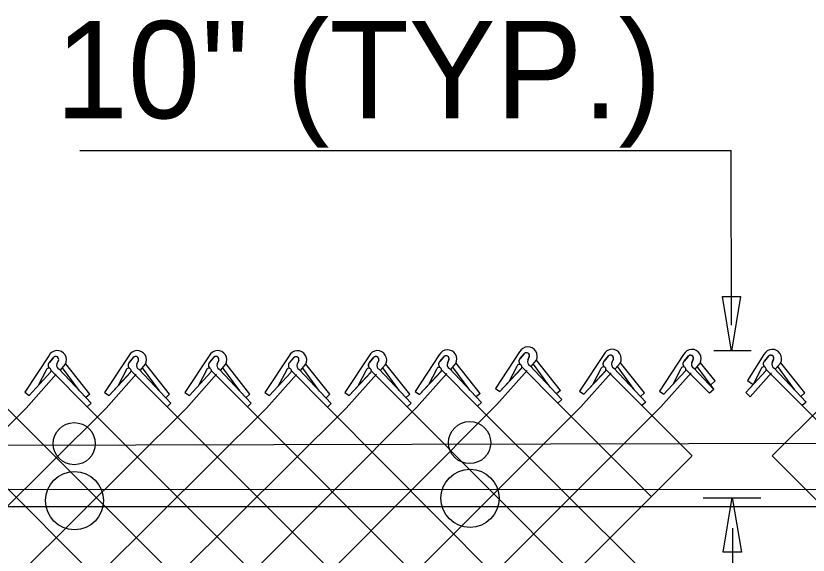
# Model space of a CAD drawing. Extents: x 0 to 2.85, y -0.1 to 1.83.
# Drawn here: x 1.3272 to 1.407, y 1.3817 to 1.436 of the extents above; entities that cross this region are included whole.
import ezdxf

# ---------------------------------------------------------------- set-up
doc = ezdxf.new("R2010")
doc.units = 0
for name, color, linetype in [('CT_Dimensions', 7, 'Continuous'), ('sb_Chainlink Fence', 7, 'Continuous'), ('sb_Existing Structural Steel', 7, 'Continuous')]:
    doc.layers.add(name, color=color, linetype=linetype)

msp = doc.modelspace()

# ---------------------------------------------------------------- linework, layer by layer
at = {"layer": 'CT_Dimensions'}
for p, q in [((1.333672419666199, 1.4224212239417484), (1.3992727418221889, 1.4224212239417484)), ((1.3993275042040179, 1.404847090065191), (1.3992727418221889, 1.4224212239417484)), ((1.397543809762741, 1.4022854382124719), (1.4012953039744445, 1.4022854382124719)), ((1.3964543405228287, 1.3874493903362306), (1.4022773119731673, 1.3874493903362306)), ((1.399430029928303, 1.376108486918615), (1.399430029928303, 1.3843877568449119))]:
    msp.add_line(p, q, dxfattribs=at)
for points in [[(1.4002339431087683, 1.407721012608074), (1.3993178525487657, 1.4022244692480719), (1.3984017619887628, 1.407721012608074)], [(1.398477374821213, 1.3819714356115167), (1.3993934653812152, 1.3874679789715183), (1.4003095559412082, 1.3819714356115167)]]:
    msp.add_lwpolyline(points, close=True, dxfattribs=at)
at = {"layer": 'sb_Chainlink Fence'}
for p, q in [((1.330548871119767, 1.401759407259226), (1.3281123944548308, 1.3980704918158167)), ((1.330596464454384, 1.4010906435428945), (1.3310415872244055, 1.4016177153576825)), ((1.331000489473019, 1.401574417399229), (1.330596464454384, 1.4010906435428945)), ((1.338601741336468, 1.401753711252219), (1.33616526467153, 1.3980647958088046)), ((1.3386493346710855, 1.4010849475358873), (1.339094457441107, 1.4016120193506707)), ((1.3390533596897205, 1.401568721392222), (1.3386493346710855, 1.4010849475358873)), ((1.3466944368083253, 1.401756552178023), (1.3442579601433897, 1.3980676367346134)), ((1.3467420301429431, 1.4010877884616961), (1.3471871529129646, 1.4016148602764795)), ((1.3471460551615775, 1.401571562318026), (1.3467420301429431, 1.4010877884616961)), ((1.3547479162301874, 1.4017361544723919), (1.3523114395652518, 1.3980472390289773)), ((1.3547955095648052, 1.40106739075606), (1.3552406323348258, 1.4015944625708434)), ((1.3551995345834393, 1.4015511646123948), (1.3547955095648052, 1.40106739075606)), ((1.3628021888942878, 1.401752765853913), (1.36036571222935, 1.3980638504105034)), ((1.3628497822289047, 1.401084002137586), (1.3632949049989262, 1.4016110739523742)), ((1.3632538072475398, 1.401567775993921), (1.3628497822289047, 1.401084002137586)), ((1.3698771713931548, 1.4018324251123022), (1.3674406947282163, 1.3981435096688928)), ((1.369924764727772, 1.4011636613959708), (1.3703698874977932, 1.4016907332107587)), ((1.370328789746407, 1.40164743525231), (1.369924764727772, 1.4011636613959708)), ((1.3779722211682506, 1.4021346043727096), (1.375535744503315, 1.3984456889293)), ((1.3780198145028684, 1.401465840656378), (1.378464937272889, 1.401992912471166)), ((1.3784238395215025, 1.4019496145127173), (1.3780198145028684, 1.401465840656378)), ((1.3789459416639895, 1.401664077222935), (1.3787823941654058, 1.4013097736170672)), ((1.3787830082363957, 1.401322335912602), (1.3789456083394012, 1.4016560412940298)), ((1.3864391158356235, 1.401884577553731), (1.3840026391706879, 1.3981956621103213)), ((1.3864867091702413, 1.4012158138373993), (1.3869318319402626, 1.4017428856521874)), ((1.3868907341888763, 1.4016995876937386), (1.3864867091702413, 1.4012158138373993)), ((1.394491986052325, 1.4018788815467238), (1.3920555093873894, 1.3981899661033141)), ((1.3945395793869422, 1.4012101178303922), (1.3949847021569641, 1.4017371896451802)), ((1.3949436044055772, 1.4016938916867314), (1.3945395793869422, 1.4012101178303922)), ((1.4025846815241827, 1.4018817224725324), (1.4009332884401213, 1.399278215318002)), ((1.4026322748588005, 1.401212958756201), (1.4030773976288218, 1.4017400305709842)), ((1.4030362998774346, 1.4016967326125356), (1.4026322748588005, 1.401212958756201)), ((1.331522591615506, 1.4012888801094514), (1.3313590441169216, 1.4009345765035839)), ((1.3313596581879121, 1.4009471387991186), (1.3315222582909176, 1.4012808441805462)), ((1.3317059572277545, 1.4002996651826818), (1.3322011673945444, 1.4008858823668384)), ((1.3317125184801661, 1.4003085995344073), (1.3322036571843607, 1.4008879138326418)), ((1.3322011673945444, 1.4008858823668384), (1.3322375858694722, 1.4009539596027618)), ((1.3322375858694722, 1.4009539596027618), (1.3322686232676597, 1.4010268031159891)), ((1.3346619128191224, 1.397894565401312), (1.3322490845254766, 1.4009292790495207)), ((1.3395754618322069, 1.4012831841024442), (1.339411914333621, 1.4009288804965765)), ((1.339412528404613, 1.4009414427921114), (1.3395751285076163, 1.401275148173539)), ((1.339758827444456, 1.4002939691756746), (1.340254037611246, 1.4008801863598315)), ((1.3397653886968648, 1.4003029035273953), (1.3402565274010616, 1.4008822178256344)), ((1.340254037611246, 1.4008801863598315), (1.340290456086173, 1.4009482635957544)), ((1.340290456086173, 1.4009482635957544), (1.3403214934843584, 1.4010211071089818)), ((1.3427147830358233, 1.397888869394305), (1.3403019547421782, 1.4009235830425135)), ((1.3476681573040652, 1.4012860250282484), (1.3475046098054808, 1.4009317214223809)), ((1.3475052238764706, 1.4009442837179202), (1.3476678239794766, 1.401277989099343)), ((1.3478515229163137, 1.4002968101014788), (1.3483467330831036, 1.4008830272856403)), ((1.347858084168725, 1.4003057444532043), (1.34834922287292, 1.4008850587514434)), ((1.3483467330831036, 1.4008830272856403), (1.3483831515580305, 1.4009511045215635)), ((1.3483831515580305, 1.4009511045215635), (1.348414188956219, 1.4010239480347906)), ((1.350807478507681, 1.3978917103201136), (1.3483946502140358, 1.4009264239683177)), ((1.3557216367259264, 1.4012656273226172), (1.3555580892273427, 1.4009113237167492)), ((1.3555587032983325, 1.4009238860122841), (1.355721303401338, 1.4012575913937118)), ((1.3559050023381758, 1.4002764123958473), (1.3564002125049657, 1.4008626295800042)), ((1.3559115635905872, 1.4002853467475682), (1.356402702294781, 1.4008646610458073)), ((1.3564002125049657, 1.4008626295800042), (1.3564366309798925, 1.4009307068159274)), ((1.3564366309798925, 1.4009307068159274), (1.35646766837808, 1.4010035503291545)), ((1.3588609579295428, 1.3978713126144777), (1.356448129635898, 1.4009060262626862)), ((1.3637759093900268, 1.401282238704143), (1.363612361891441, 1.4009279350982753)), ((1.363612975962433, 1.4009404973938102), (1.3637755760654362, 1.4012742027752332)), ((1.3639592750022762, 1.4002930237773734), (1.364454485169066, 1.40087924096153)), ((1.3639658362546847, 1.4003019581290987), (1.3644569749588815, 1.4008812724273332)), ((1.364454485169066, 1.40087924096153), (1.364490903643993, 1.4009473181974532)), ((1.364490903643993, 1.4009473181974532), (1.3645219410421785, 1.4010201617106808)), ((1.3669152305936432, 1.3978879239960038), (1.3645024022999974, 1.4009226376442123)), ((1.3708508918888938, 1.4013618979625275), (1.3706873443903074, 1.40100759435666)), ((1.3706879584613, 1.401020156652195), (1.3708505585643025, 1.4013538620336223)), ((1.3710342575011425, 1.4003726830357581), (1.371529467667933, 1.4009589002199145)), ((1.3710408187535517, 1.4003816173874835), (1.3715319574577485, 1.4009609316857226)), ((1.371529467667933, 1.4009589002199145), (1.37156588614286, 1.4010269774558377)), ((1.37156588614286, 1.4010269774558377), (1.3715969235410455, 1.4010998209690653)), ((1.3739902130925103, 1.3979675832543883), (1.3715773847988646, 1.4010022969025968)), ((1.3789941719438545, 1.4007703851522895), (1.3822196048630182, 1.397343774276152)), ((1.379129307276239, 1.4006748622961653), (1.379624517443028, 1.401261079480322)), ((1.3791358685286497, 1.4006837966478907), (1.3796270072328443, 1.4012631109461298)), ((1.3810462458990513, 1.398601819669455), (1.3793491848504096, 1.400911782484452)), ((1.379624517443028, 1.401261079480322), (1.3796609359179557, 1.4013291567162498)), ((1.3796609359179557, 1.4013291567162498), (1.3796919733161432, 1.4014020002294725)), ((1.382085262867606, 1.3982697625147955), (1.379672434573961, 1.4013044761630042)), ((1.3874128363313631, 1.401414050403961), (1.3872492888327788, 1.4010597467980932)), ((1.3872499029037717, 1.4010723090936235), (1.3874125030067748, 1.4014060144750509)), ((1.3875962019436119, 1.4004248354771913), (1.388091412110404, 1.401011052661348)), ((1.3876027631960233, 1.400433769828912), (1.3880939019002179, 1.401013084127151)), ((1.388091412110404, 1.401011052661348), (1.3881278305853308, 1.4010791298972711)), ((1.3881278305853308, 1.4010791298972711), (1.388158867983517, 1.4011519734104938)), ((1.3905521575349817, 1.3980197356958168), (1.3881393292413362, 1.4010544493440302)), ((1.395465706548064, 1.4014083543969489), (1.3953021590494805, 1.4010540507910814)), ((1.3953027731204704, 1.4010666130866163), (1.3954653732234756, 1.401400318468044)), ((1.3956490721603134, 1.4004191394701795), (1.3961442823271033, 1.4010053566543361)), ((1.3956556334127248, 1.4004280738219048), (1.3961467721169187, 1.401007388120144)), ((1.3961442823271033, 1.4010053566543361), (1.3961807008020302, 1.4010734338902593)), ((1.3961807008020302, 1.4010734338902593), (1.396211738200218, 1.4011462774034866)), ((1.3976529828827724, 1.3992114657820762), (1.3961921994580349, 1.4010487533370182)), ((1.4035584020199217, 1.4014111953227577), (1.403394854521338, 1.4010568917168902)), ((1.4033954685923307, 1.401069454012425), (1.4035580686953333, 1.4014031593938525)), ((1.403741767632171, 1.4004219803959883), (1.4042369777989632, 1.4010081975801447)), ((1.4037483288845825, 1.4004309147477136), (1.404239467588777, 1.401010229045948)), ((1.4042369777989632, 1.4010081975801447), (1.40427339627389, 1.4010762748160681)), ((1.40427339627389, 1.4010762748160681), (1.4043044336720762, 1.4011491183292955)), ((1.406697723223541, 1.3980168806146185), (1.4042848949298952, 1.401051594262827)), ((1.3282564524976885, 1.3964829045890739), (1.3312917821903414, 1.3999005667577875)), ((1.3285583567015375, 1.3977658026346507), (1.330728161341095, 1.4001031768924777)), ((1.3285583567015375, 1.3977658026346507), (1.3307143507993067, 1.4000894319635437)), ((1.3302714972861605, 1.400303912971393), (1.3294598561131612, 1.3987523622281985)), ((1.3307731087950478, 1.4002526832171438), (1.3344004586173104, 1.396609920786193)), ((1.331570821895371, 1.4003951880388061), (1.334796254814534, 1.3969685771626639)), ((1.3336228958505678, 1.3982266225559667), (1.331925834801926, 1.4005365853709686)), ((1.3366112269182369, 1.3977601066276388), (1.338781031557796, 1.4000974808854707)), ((1.3366112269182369, 1.3977601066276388), (1.3387672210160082, 1.4000837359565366)), ((1.3383243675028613, 1.4002982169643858), (1.3375127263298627, 1.3987466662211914)), ((1.3388259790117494, 1.4002469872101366), (1.342453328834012, 1.396604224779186)), ((1.3396236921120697, 1.400389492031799), (1.3428491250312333, 1.396962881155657)), ((1.3416757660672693, 1.3982209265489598), (1.3399787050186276, 1.4005308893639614)), ((1.3447039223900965, 1.3977629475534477), (1.3468737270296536, 1.4001003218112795)), ((1.3447039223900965, 1.3977629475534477), (1.3468599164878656, 1.4000865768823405)), ((1.3464170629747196, 1.4003010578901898), (1.3456054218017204, 1.3987495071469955)), ((1.346918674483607, 1.4002498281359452), (1.3505460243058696, 1.396607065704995)), ((1.3477163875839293, 1.4003923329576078), (1.350941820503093, 1.3969657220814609)), ((1.349768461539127, 1.3982237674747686), (1.3480714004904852, 1.4005337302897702)), ((1.3527574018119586, 1.3977425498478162), (1.3549272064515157, 1.4000799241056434)), ((1.3527574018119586, 1.3977425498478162), (1.3549133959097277, 1.4000661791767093)), ((1.3544705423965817, 1.4002806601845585), (1.3536589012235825, 1.398729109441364)), ((1.354972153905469, 1.4002294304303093), (1.3585995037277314, 1.3965866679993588)), ((1.3557698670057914, 1.4003719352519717), (1.358995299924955, 1.3969453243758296)), ((1.3578219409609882, 1.3982033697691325), (1.3561248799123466, 1.4005133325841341)), ((1.360811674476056, 1.3977591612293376), (1.362981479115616, 1.4000965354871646)), ((1.360811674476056, 1.3977591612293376), (1.3629676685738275, 1.4000827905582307)), ((1.3625248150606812, 1.4002972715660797), (1.361713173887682, 1.3987457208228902)), ((1.3630264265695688, 1.4002460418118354), (1.3666537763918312, 1.3966032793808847)), ((1.3638241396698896, 1.4003885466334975), (1.3670495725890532, 1.3969619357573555)), ((1.3658762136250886, 1.3982199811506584), (1.364179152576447, 1.4005299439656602)), ((1.3675847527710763, 1.39655592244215), (1.3706200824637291, 1.3999735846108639)), ((1.367886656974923, 1.397838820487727), (1.370056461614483, 1.4001761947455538)), ((1.367886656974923, 1.397838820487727), (1.3700426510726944, 1.4001624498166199)), ((1.3695997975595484, 1.400376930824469), (1.3687881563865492, 1.3988253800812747)), ((1.3701014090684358, 1.40032570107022), (1.3737287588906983, 1.3966829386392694)), ((1.3708991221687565, 1.4004682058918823), (1.3741245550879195, 1.3970415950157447)), ((1.3729511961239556, 1.3982996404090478), (1.371254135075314, 1.4006096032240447)), ((1.3756798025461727, 1.3968581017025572), (1.378715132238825, 1.4002757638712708)), ((1.3759817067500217, 1.398140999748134), (1.3781515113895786, 1.4004783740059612)), ((1.3759817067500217, 1.398140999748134), (1.3781377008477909, 1.4004646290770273)), ((1.377694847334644, 1.4006791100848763), (1.3768832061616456, 1.399127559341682)), ((1.3781964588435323, 1.4006278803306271), (1.3818238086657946, 1.3969851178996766)), ((1.3841466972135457, 1.3966080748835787), (1.3871820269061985, 1.4000257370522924)), ((1.3844486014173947, 1.3978909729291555), (1.3866184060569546, 1.4002283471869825)), ((1.3844486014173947, 1.3978909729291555), (1.3866045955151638, 1.4002146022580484)), ((1.38616174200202, 1.4004290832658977), (1.3853501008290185, 1.398877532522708)), ((1.3866633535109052, 1.4003778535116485), (1.3902907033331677, 1.396735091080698)), ((1.3874610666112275, 1.4005203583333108), (1.3906864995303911, 1.3970937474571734)), ((1.389513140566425, 1.3983517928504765), (1.3878160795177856, 1.4006617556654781)), ((1.3921995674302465, 1.3966023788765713), (1.3952348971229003, 1.4000200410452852)), ((1.3925014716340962, 1.3978852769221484), (1.3946712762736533, 1.4002226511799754)), ((1.3925014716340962, 1.3978852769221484), (1.3946574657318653, 1.4002089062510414)), ((1.3942146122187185, 1.4004233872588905), (1.39340297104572, 1.3988718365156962)), ((1.394716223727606, 1.4003721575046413), (1.3970972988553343, 1.3979809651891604)), ((1.395513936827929, 1.4005146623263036), (1.397531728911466, 1.398371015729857)), ((1.3975443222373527, 1.3983756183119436), (1.3958689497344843, 1.400656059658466)), ((1.4007617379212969, 1.3980509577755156), (1.4027639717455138, 1.400225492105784)), ((1.4011838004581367, 1.3985235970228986), (1.402750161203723, 1.40021174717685)), ((1.4011904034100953, 1.3976164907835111), (1.4033275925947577, 1.400022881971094)), ((1.402307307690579, 1.4004262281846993), (1.4014956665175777, 1.398874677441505)), ((1.4028089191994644, 1.40037499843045), (1.4064362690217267, 1.3967322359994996)), ((1.4036066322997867, 1.4005175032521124), (1.4068320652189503, 1.3970908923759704)), ((1.4056587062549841, 1.3983489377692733), (1.4039616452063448, 1.400658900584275)), ((1.33630932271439, 1.3964772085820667), (1.339344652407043, 1.3998948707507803)), ((1.3444020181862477, 1.3964800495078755), (1.3474373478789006, 1.3998977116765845)), ((1.3524554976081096, 1.3964596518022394), (1.3554908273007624, 1.399877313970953)), ((1.3605097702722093, 1.3964762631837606), (1.3635450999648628, 1.3998939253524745)), ((1.3976529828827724, 1.3992114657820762), (1.397222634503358, 1.3988214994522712)), ((1.4009332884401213, 1.399278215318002), (1.4014956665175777, 1.398874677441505)), ((1.375535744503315, 1.3984456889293), (1.3759817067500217, 1.398140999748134)), ((1.397531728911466, 1.398371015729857), (1.3970987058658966, 1.397978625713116)), ((1.3281123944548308, 1.3980704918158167), (1.3285583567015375, 1.3977658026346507)), ((1.3346619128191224, 1.397894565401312), (1.3342661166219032, 1.3975359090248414)), ((1.33616526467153, 1.3980647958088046), (1.3366112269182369, 1.3977601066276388)), ((1.3427147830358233, 1.397888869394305), (1.3423189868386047, 1.3975302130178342)), ((1.3442579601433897, 1.3980676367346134), (1.3447039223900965, 1.3977629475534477)), ((1.350807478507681, 1.3978917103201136), (1.3504116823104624, 1.3975330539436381)), ((1.3523114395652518, 1.3980472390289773), (1.3527574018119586, 1.3977425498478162)), ((1.3588609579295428, 1.3978713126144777), (1.3584651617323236, 1.397512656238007)), ((1.36036571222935, 1.3980638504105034), (1.360811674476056, 1.3977591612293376)), ((1.3669152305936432, 1.3978879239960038), (1.366519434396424, 1.397529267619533)), ((1.3674406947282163, 1.3981435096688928), (1.367886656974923, 1.397838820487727)), ((1.3739902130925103, 1.3979675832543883), (1.3735944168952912, 1.3976089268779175)), ((1.382085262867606, 1.3982697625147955), (1.3816894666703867, 1.397911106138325)), ((1.3840026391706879, 1.3981956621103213), (1.3844486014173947, 1.3978909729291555)), ((1.3905521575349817, 1.3980197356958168), (1.3901563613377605, 1.397661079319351)), ((1.3920555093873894, 1.3981899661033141), (1.3925014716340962, 1.3978852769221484)), ((1.4007617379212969, 1.3980509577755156), (1.4011904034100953, 1.3976164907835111)), ((1.406697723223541, 1.3980168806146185), (1.4063019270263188, 1.3976582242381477)), ((1.2691732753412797, 1.2899304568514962), (1.3756798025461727, 1.3968581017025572)), ((1.317879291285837, 1.3968433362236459), (1.4247986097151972, 1.290038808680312)), ((1.3259335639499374, 1.396859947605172), (1.4329119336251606, 1.2899438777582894)), ((1.334796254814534, 1.3969685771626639), (1.3344004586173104, 1.396609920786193)), ((1.3428491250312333, 1.396962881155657), (1.342453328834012, 1.396604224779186)), ((1.350941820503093, 1.3969657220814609), (1.3505460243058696, 1.396607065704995)), ((1.358995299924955, 1.3969453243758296), (1.3585995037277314, 1.3965866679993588)), ((1.3670495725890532, 1.3969619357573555), (1.3666537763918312, 1.3966032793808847)), ((1.3741245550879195, 1.3970415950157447), (1.3737287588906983, 1.3966829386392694)), ((1.3822196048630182, 1.397343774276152), (1.3818238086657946, 1.3969851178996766)), ((1.3818238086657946, 1.3969851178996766), (1.3912193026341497, 1.3875857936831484)), ((1.3906864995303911, 1.3970937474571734), (1.3902907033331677, 1.396735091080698)), ((1.3902907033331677, 1.396735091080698), (1.3953598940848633, 1.391655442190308)), ((1.4068320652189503, 1.3970908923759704), (1.4064362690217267, 1.3967322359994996)), ((1.4064362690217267, 1.3967322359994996), (1.4554980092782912, 1.3475362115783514)), ((1.2203680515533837, 1.2892561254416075), (1.3282564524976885, 1.3964829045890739)), ((1.2286213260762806, 1.289436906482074), (1.33630932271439, 1.3964772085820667)), ((1.236559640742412, 1.2892719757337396), (1.3444020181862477, 1.3964800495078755)), ((1.2448086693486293, 1.2895248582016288), (1.3524554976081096, 1.3964596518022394)), ((1.2529972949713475, 1.2897002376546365), (1.3605097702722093, 1.3964762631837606)), ((1.2610501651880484, 1.2897059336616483), (1.3675847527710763, 1.39655592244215)), ((1.2771338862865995, 1.2897935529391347), (1.3841466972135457, 1.3966080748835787)), ((1.2855302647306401, 1.2900829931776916), (1.3921995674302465, 1.3966023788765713)), ((1.3344004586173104, 1.396609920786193), (1.440911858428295, 1.2901536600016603)), ((1.342453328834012, 1.396604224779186), (1.4490435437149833, 1.2901329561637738)), ((1.3505460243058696, 1.396607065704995), (1.4276839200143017, 1.3195015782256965)), ((1.3585995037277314, 1.3965866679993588), (1.4313940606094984, 1.3234575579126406)), ((1.3666537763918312, 1.3966032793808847), (1.4314088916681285, 1.3315628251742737)), ((1.3737287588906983, 1.3966829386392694), (1.4354146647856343, 1.3352501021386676)), ((1.403419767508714, 1.3916699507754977), (1.408345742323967, 1.396584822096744)), ((1.2934769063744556, 1.2899821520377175), (1.3953306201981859, 1.3916525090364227)), ((1.4034074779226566, 1.3916548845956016), (1.4514459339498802, 1.3435158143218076))]:
    msp.add_line(p, q, dxfattribs=at)
for centre, radius, start, end in [((1.3707156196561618, 1.4014176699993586), 0.0009354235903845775, 330.7731305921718, 153.67978342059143), ((1.3788106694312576, 1.4017198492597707), 0.0009354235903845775, 330.7731305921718, 153.67978342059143), ((1.3872775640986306, 1.401469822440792), 0.0009354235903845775, 330.7731305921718, 153.67978342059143), ((1.395330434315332, 1.4014641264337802), 0.0009354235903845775, 330.7731305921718, 153.67978342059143), ((1.4034231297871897, 1.401466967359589), 0.0009354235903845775, 330.7731305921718, 153.67978342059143), ((1.331387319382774, 1.4013446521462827), 0.0009354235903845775, 330.7731305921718, 153.67978342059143), ((1.3312333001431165, 1.401380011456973), 0.00030330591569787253, 342.5147558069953, 140.13680881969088), ((1.3312343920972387, 1.4013814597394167), 0.00030494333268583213, 340.73435754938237, 129.21739859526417), ((1.339440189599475, 1.4013389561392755), 0.0009354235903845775, 330.7731305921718, 153.67978342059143), ((1.339286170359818, 1.4013743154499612), 0.00030330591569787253, 342.5147558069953, 140.13680881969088), ((1.3392872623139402, 1.4013757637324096), 0.00030494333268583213, 340.73435754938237, 129.21739859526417), ((1.3475328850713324, 1.4013417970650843), 0.0009354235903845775, 330.7731305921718, 153.67978342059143), ((1.3473788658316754, 1.40137715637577), 0.00030330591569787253, 342.5147558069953, 140.13680881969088), ((1.3473799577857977, 1.4013786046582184), 0.00030494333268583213, 340.73435754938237, 129.21739859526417), ((1.3555863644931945, 1.4013213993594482), 0.0009354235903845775, 330.7731305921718, 153.67978342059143), ((1.3554323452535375, 1.4013567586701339), 0.00030330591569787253, 342.5147558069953, 140.13680881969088), ((1.3554334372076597, 1.4013582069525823), 0.00030494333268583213, 340.73435754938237, 129.21739859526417), ((1.3636406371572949, 1.401338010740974), 0.0009354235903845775, 330.7731305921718, 153.67978342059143), ((1.363486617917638, 1.4013733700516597), 0.00030330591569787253, 342.5147558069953, 140.13680881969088), ((1.3634877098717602, 1.4013748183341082), 0.00030494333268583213, 340.73435754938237, 129.21739859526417), ((1.3705616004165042, 1.4014530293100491), 0.00030330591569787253, 342.5147558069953, 140.13680881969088), ((1.3705626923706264, 1.4014544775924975), 0.00030494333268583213, 340.73435754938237, 129.21739859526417), ((1.3786566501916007, 1.4017552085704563), 0.00030330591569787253, 342.5147558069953, 140.13680881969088), ((1.378657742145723, 1.4017566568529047), 0.00030494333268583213, 340.73435754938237, 129.21739859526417), ((1.3871235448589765, 1.4015051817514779), 0.00030330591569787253, 342.5147558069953, 140.13680881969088), ((1.3871246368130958, 1.4015066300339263), 0.00030494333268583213, 340.73435754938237, 129.21739859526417), ((1.3951764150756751, 1.4014994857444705), 0.00030330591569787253, 342.5147558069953, 140.13680881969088), ((1.3951775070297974, 1.4015009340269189), 0.00030494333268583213, 340.73435754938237, 129.21739859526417), ((1.403269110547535, 1.4015023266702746), 0.00030330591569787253, 342.5147558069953, 140.13680881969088), ((1.403270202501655, 1.401503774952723), 0.00030494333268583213, 340.73435754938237, 129.21739859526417), ((1.3308559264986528, 1.4008073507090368), 0.0003843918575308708, 140.20166010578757, 233.0052527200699), ((1.3308664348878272, 1.4008078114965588), 0.0003909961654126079, 133.66718540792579, 232.2343578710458), ((1.3317467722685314, 1.4007752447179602), 0.00041880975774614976, 156.48328493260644, 245.15783350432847), ((1.3389087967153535, 1.4008016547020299), 0.0003843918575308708, 140.20166010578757, 233.0052527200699), ((1.3389193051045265, 1.4008021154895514), 0.0003909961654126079, 133.66718540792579, 232.2343578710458), ((1.339799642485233, 1.4007695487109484), 0.00041880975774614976, 156.48328493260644, 245.15783350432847), ((1.3470014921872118, 1.4008044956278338), 0.0003843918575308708, 140.20166010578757, 233.0052527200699), ((1.3470120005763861, 1.4008049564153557), 0.0003909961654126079, 133.66718540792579, 232.2343578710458), ((1.3478923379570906, 1.4007723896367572), 0.00041880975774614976, 156.48328493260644, 245.15783350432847), ((1.3550549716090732, 1.4007840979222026), 0.0003843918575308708, 140.20166010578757, 233.0052527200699), ((1.3550654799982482, 1.400784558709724), 0.0003909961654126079, 133.66718540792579, 232.2343578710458), ((1.355945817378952, 1.400751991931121), 0.00041880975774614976, 156.48328493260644, 245.15783350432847), ((1.3631092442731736, 1.4008007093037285), 0.0003843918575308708, 140.20166010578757, 233.0052527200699), ((1.3631197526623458, 1.4008011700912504), 0.0003909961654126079, 133.66718540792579, 232.2343578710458), ((1.3640000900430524, 1.4007686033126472), 0.00041880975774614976, 156.48328493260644, 245.15783350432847), ((1.3701842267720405, 1.400880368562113), 0.0003843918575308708, 140.20166010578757, 233.0052527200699), ((1.3701947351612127, 1.4008808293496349), 0.0003909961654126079, 133.66718540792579, 232.2343578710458), ((1.3710750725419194, 1.4008482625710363), 0.00041880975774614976, 156.48328493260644, 245.15783350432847), ((1.3779468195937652, 1.400634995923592), 0.00025580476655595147, 319.02146199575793, 170.0695590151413), ((1.3782792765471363, 1.4011825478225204), 0.0003843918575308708, 140.20166010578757, 233.0052527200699), ((1.3782897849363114, 1.401183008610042), 0.0003909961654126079, 133.66718540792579, 232.2343578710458), ((1.379170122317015, 1.4011504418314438), 0.00041880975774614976, 156.48328493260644, 245.15783350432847), ((1.38674617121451, 1.4009325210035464), 0.0003843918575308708, 140.20166010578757, 233.0052527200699), ((1.3867566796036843, 1.400932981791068), 0.0003909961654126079, 133.66718540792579, 232.2343578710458), ((1.3876370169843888, 1.4009004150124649), 0.00041880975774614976, 156.48328493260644, 245.15783350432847), ((1.3947990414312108, 1.4009268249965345), 0.0003843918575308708, 140.20166010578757, 233.0052527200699), ((1.3948095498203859, 1.4009272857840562), 0.0003909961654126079, 133.66718540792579, 232.2343578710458), ((1.3956898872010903, 1.400894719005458), 0.00041880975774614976, 156.48328493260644, 245.15783350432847), ((1.4028917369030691, 1.4009296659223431), 0.0003843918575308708, 140.20166010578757, 233.0052527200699), ((1.4029022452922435, 1.400930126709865), 0.0003909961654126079, 133.66718540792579, 232.2343578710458), ((1.403782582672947, 1.4008975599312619), 0.00041880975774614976, 156.48328493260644, 245.15783350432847), ((1.3305234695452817, 1.4002597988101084), 0.00025580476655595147, 319.02146199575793, 170.0695590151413), ((1.3385763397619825, 1.4002541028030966), 0.00025580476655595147, 319.02146199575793, 170.0695590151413), ((1.3466690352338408, 1.4002569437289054), 0.00025580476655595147, 319.02146199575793, 170.0695590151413), ((1.354722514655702, 1.4002365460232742), 0.00025580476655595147, 319.02146199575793, 170.0695590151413), ((1.3627767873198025, 1.4002531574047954), 0.00025580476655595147, 319.02146199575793, 170.0695590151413), ((1.3698517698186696, 1.4003328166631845), 0.00025580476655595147, 319.02146199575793, 170.0695590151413), ((1.386413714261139, 1.4003849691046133), 0.00025580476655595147, 319.02146199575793, 170.0695590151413), ((1.3944665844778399, 1.4003792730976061), 0.00025580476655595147, 319.02146199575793, 170.0695590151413), ((1.4025592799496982, 1.4003821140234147), 0.00025580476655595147, 319.02146199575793, 170.0695590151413)]:
    msp.add_arc(centre, radius, start, end, dxfattribs=at)
at = {"layer": 'sb_Existing Structural Steel'}
for p, q in [((1.4847566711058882, 1.3930921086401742), (1.3081066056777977, 1.3926586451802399)), ((1.314044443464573, 1.3882984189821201), (1.478990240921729, 1.3882845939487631)), ((1.3140528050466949, 1.3865683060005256), (1.4790643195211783, 1.386545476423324))]:
    msp.add_line(p, q, dxfattribs=at)
for centre, radius in [((1.3729310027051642, 1.39300505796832), 0.0021204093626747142), ((1.3331032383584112, 1.3928931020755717), 0.0021204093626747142), ((1.3729719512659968, 1.387392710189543), 0.002929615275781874), ((1.3331286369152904, 1.3871564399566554), 0.002929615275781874)]:
    msp.add_circle(centre, radius, dxfattribs=at)

# ---------------------------------------------------------------- texts
at = {"layer": 'CT_Dimensions'}
msp.add_text("10'' (TYP.)", height=0.009801, dxfattribs=at).set_placement((1.3312161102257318, 1.425680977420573))

doc.saveas('drawing.dxf')
